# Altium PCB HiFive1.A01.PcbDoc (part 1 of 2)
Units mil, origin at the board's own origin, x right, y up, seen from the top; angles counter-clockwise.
Board outline 2700 x 2100 mil, 4 copper layers (Top Layer, GND, Power, Bottom Layer), stack 60.6 mil thick; 123 components, 93 nets, 495 pads, 264 vias.
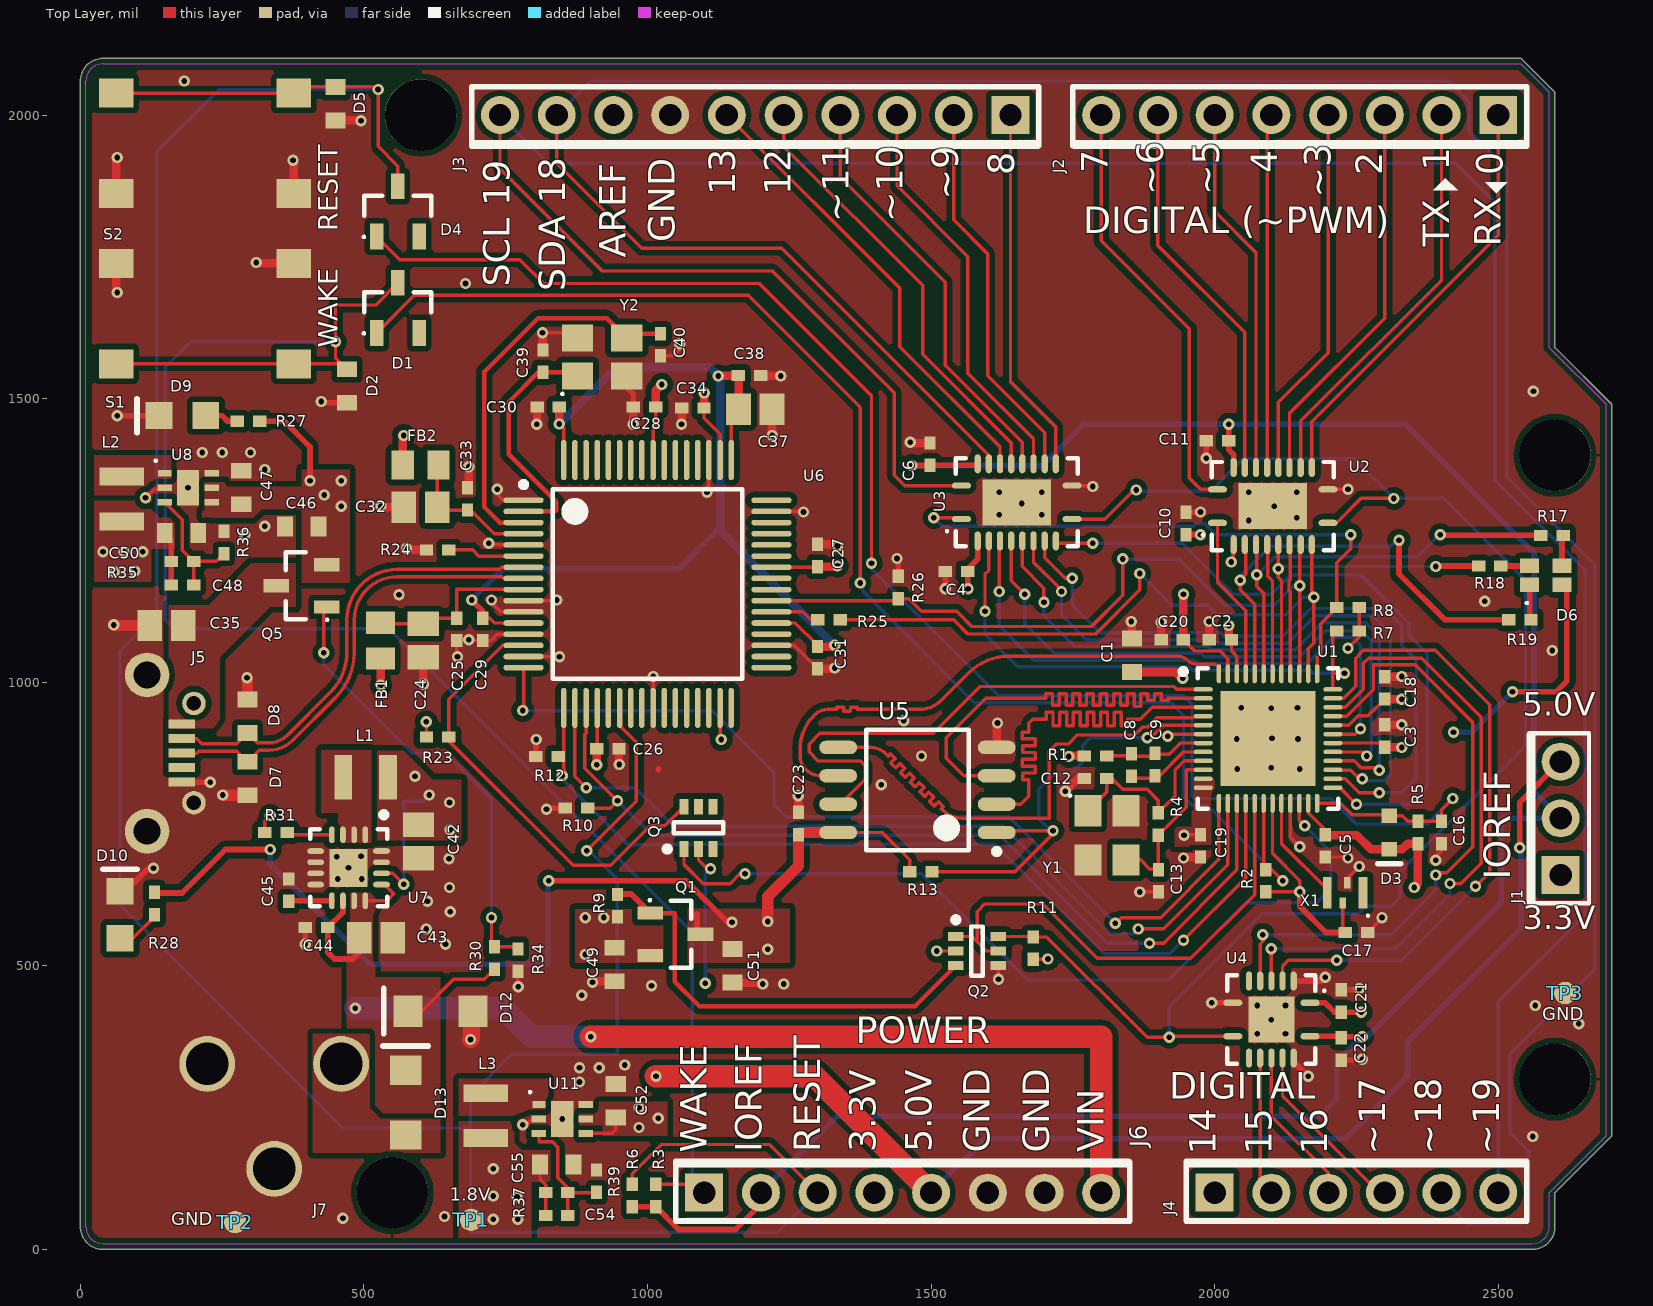
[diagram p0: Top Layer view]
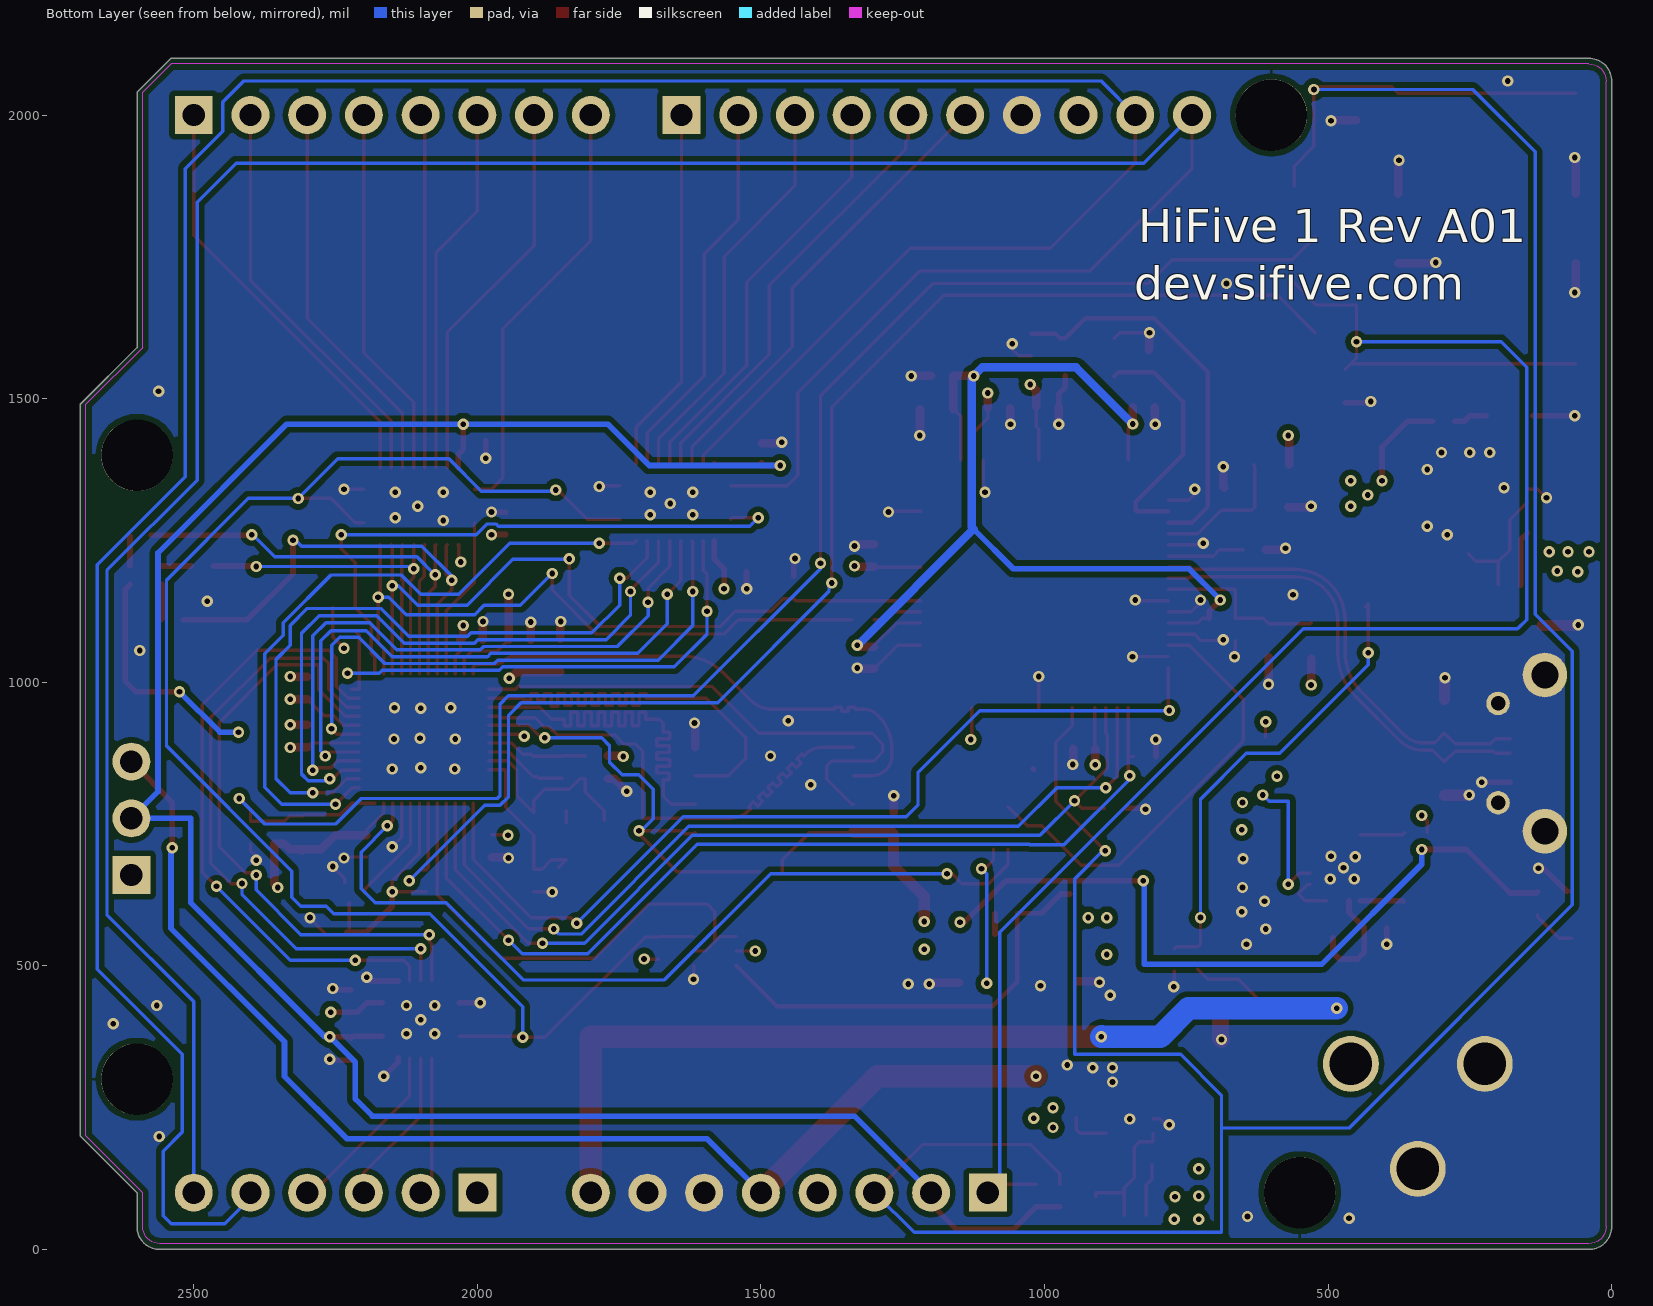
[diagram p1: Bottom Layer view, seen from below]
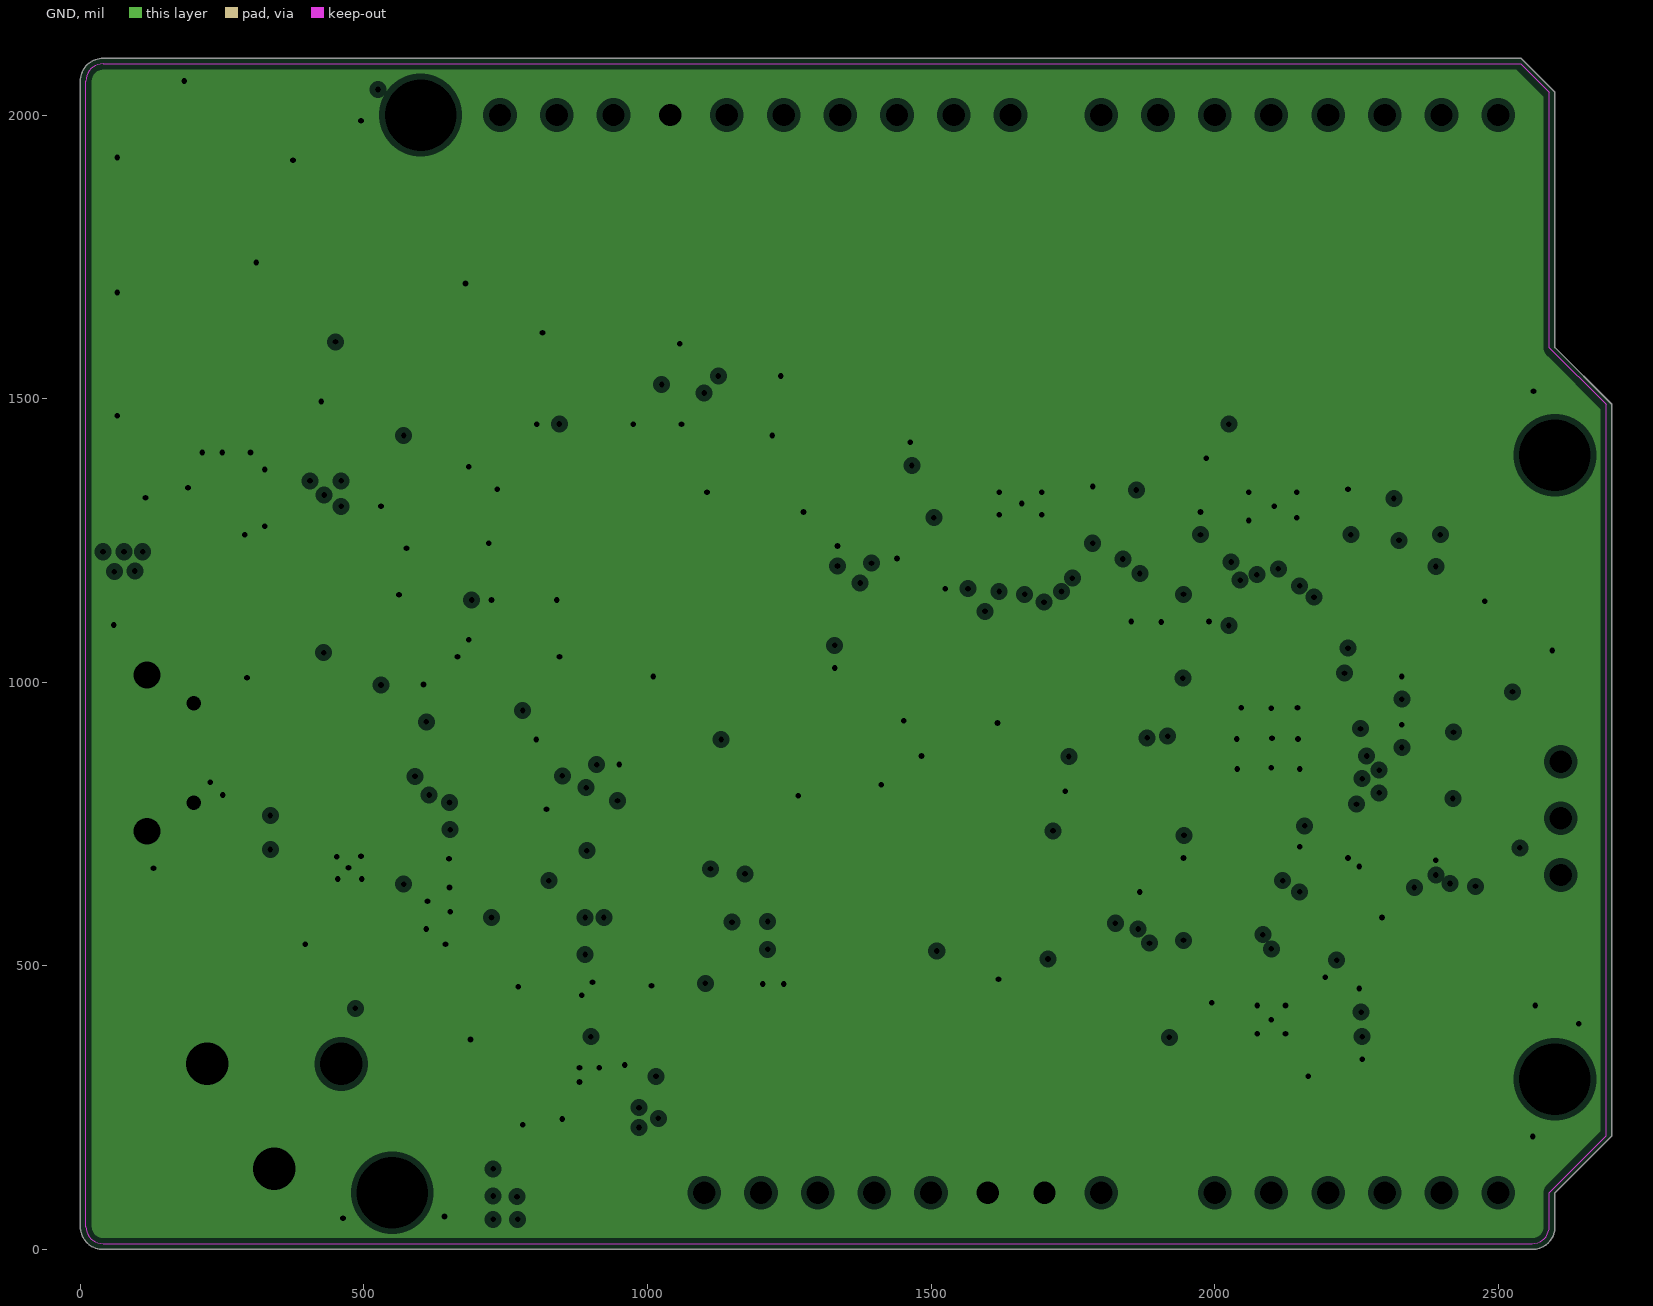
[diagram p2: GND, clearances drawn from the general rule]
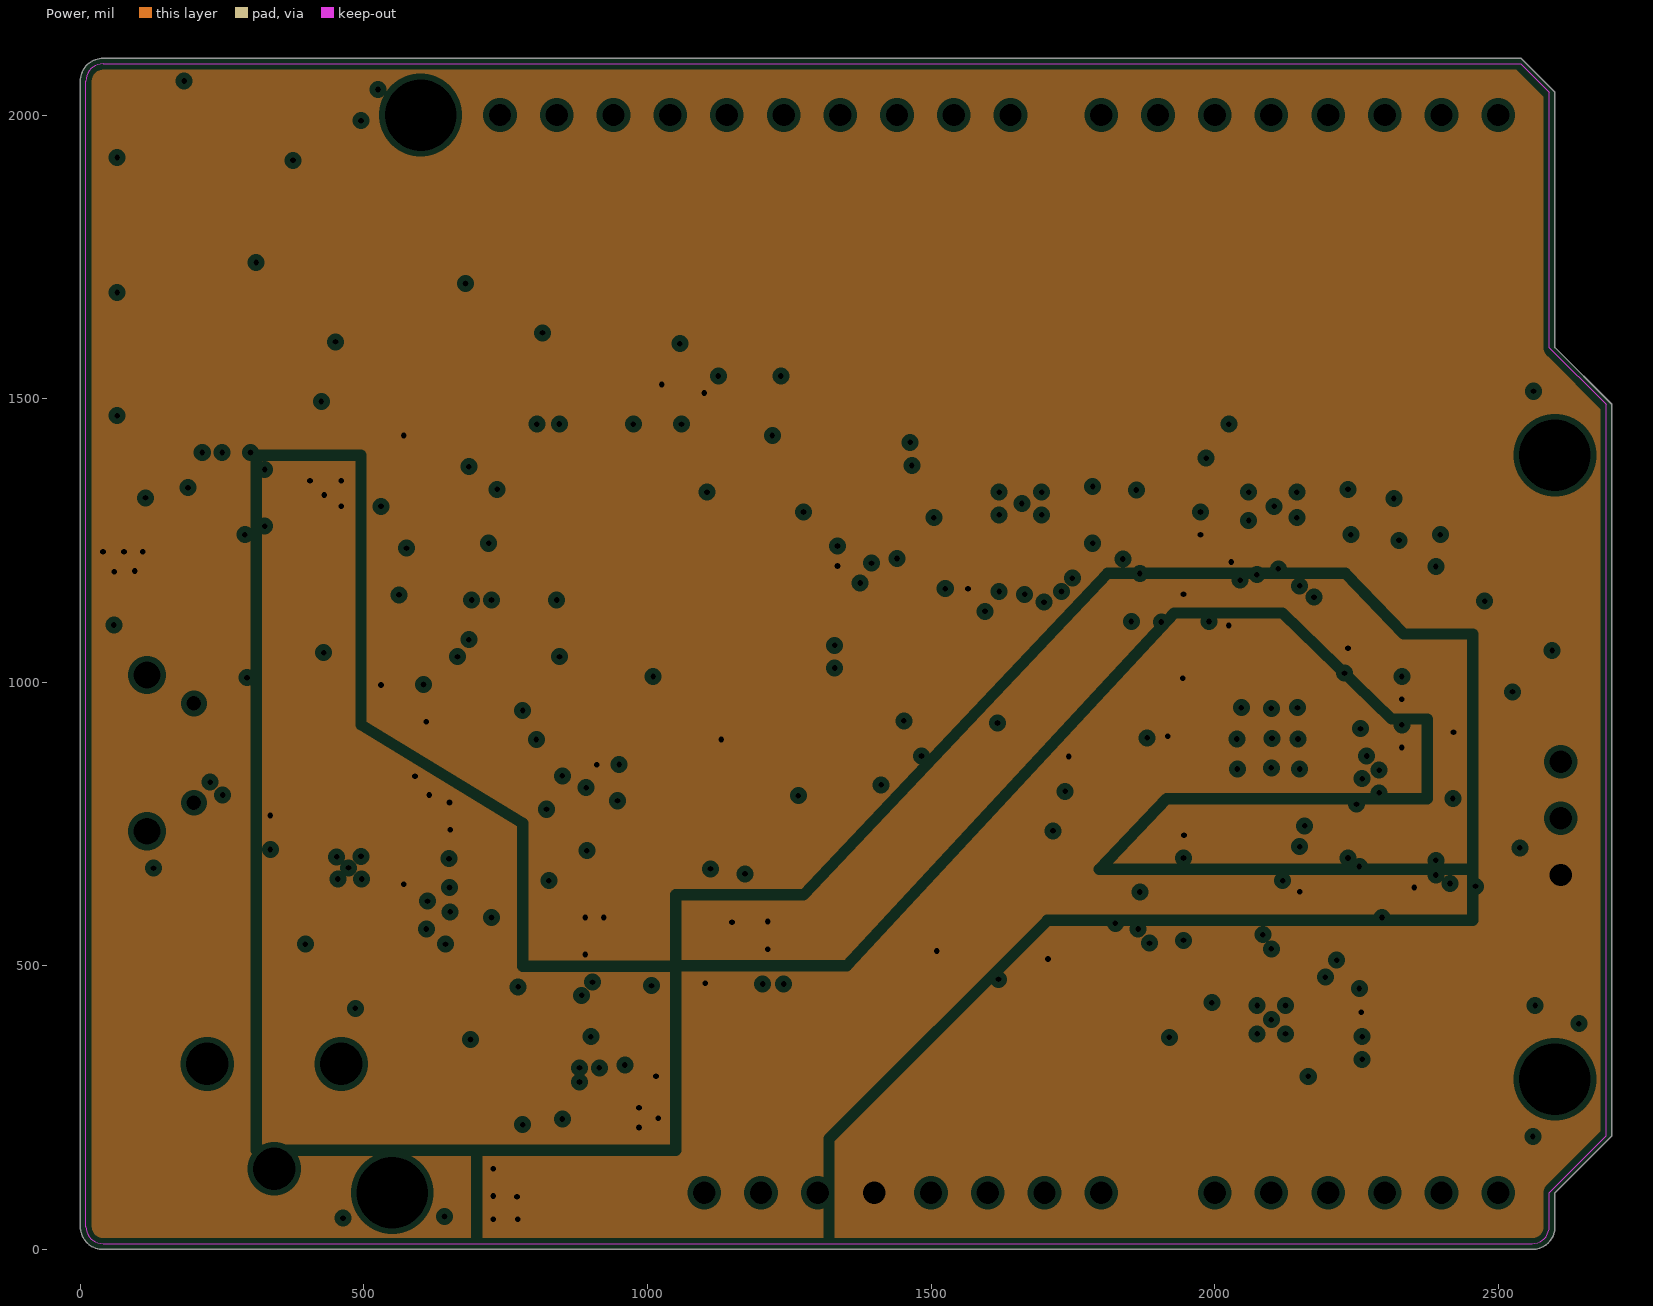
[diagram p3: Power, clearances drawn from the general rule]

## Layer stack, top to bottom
Top Solder: solder mask 0.5, Solder Resist, Dk 3.5
Top Layer: signal copper 1.4
Dielectric 1: core 4, FR-4, Dk 4.2
GND: plane copper 1.4, net GND
Dielectric 2: core 47, Dk 4.2
Power: plane copper 1.4, net (Multiple Nets)
Dielectric 3: prepreg 4, Dk 4.2
Bottom Layer: signal copper 1.4
Bottom Solder: solder mask 0.5, Solder Resist, Dk 3.5

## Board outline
0,40 0,2060 cw(c40,2060) 40,2100 2540,2100 2600,2040 2600,1590 2700,1490 2700,200 2600,100 2600,40 cw(c2560,40) 2560,0 40,0 cw(c40,40)

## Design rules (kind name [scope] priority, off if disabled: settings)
Clearance PolygonClearance [InPolygon] p1: gap=10 ignorepadtopadclearanceinfootprint=FALSE except(0: Arc-Hole Track-Hole SMDPad-Hole THPad-Hole Via-Hole Fill-Hole Poly-Hole Region-Hole Text-Hole)
Clearance [All] p2: gap=6 ignorepadtopadclearanceinfootprint=FALSE except(0: Arc-Hole Track-Hole SMDPad-Hole THPad-Hole Via-Hole Fill-Hole Poly-Hole Region-Hole Text-Hole)
ComponentClearance [All] p1: gap=1 collisioncheckmode=3 verticalgap=1 showdistances=FALSE
DiffPairsRouting DIFF90DiffPairsRouting [InDifferentialPairClass('DIFF90')] p1: maxlimit=7 minlimit=7 mostfreqgap=7 toplayer_minwidth=6 toplayer_maxwidth=6 toplayer_prefwidth=6 bottomlayer_minwidth=6 bottomlayer_maxwidth=6 bottomlayer_prefwidth=6 maxuncoupledlength=500
DiffPairsRouting [All] p2: maxlimit=10 minlimit=10 mostfreqgap=10 toplayer_minwidth=15 toplayer_maxwidth=15 toplayer_prefwidth=15 bottomlayer_minwidth=15 bottomlayer_maxwidth=15 bottomlayer_prefwidth=15 maxuncoupledlength=500
HoleSize [All] p1: absolutevalues=TRUE maxlimit=150 minlimit=1 maxpercent=80.000 minpercent=20.000
MatchedLengths QSPIMatchedLengths [InNetClass('QSPI')] p1: tolerance=50 checknetsindiffpair=FALSE checkdiffpairvsdiffpair=TRUE checkxsignals=TRUE checkothers=TRUE
MatchedLengths Diff90MatchedLengths [InDifferentialPairClass('DIFF90')] p2: tolerance=10 checknetsindiffpair=TRUE checkdiffpairvsdiffpair=FALSE checkxsignals=FALSE checkothers=FALSE
MinimumSolderMaskSliver [All] p1: minsoldermaskwidth=3
PlaneClearance [All] p1: clearance=10
PlaneConnect [All] p1: planeconnectstyle=Direct reliefexpansion=20 reliefentries=4 reliefconductorwidth=10 reliefairgap=10
PolygonConnect [All] p1: connectstyle=Direct reliefconductorwidth=10 reliefentries=4 polygonreliefangle="90 Angle" airgapwidth=10
RoutingVias [All] p1: holewidth=10 width=20 viastyle="Through Hole" minholewidth=10 minwidth=20 maxholewidth=28 maxwidth=50
SilkToSilkClearance [All] p1: silktosilkclearance=0
SilkToSolderMaskClearance [IsPad] p1: minsilkscreentomaskgap=1 clearancetoexposedcopper=TRUE
SolderMaskExpansion [All] p1: expansion=4
Width [All] p1: maxlimit=40 minlimit=6 preferedwidth=6
22 further rules are at their usual default settings.

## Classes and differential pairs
component class Freedom_E310: C1 C2 C3 C4 C5 C6 C8 C9 C10 C11 C12 C13 C16 C17 C18 C19 C20 C21 C22 C23 D1 D2 D3 D4 D5 D6 J1 J2 J3 J4 J6 Q2 R1 R2 R3 R4 R5 R6 R7 R8 R11 R13 R17 R18 R19 S1 S2 U1 U2 U3 U4 U5 X1 Y1
component class FT2232: C24 C25 C26 C27 C28 C29 C30 C31 C32 C33 C34 C35 C37 C38 C39 C40 D7 D8 FB1 FB2 J5 Q3 R10 R12 R23 R24 R25 R26 U6 Y2
component class Power: C42 C43 C44 C45 C46 C47 C48 C49 C50 C51 C52 C54 C55 D9 D10 D12 D13 GND I_VDD_1V8 J7 L1 L2 L3 Q1 Q5 R9 R27 R28 R30 R31 R34 R35 R36 R37 R39 TP1 TP2 TP3 U7 U8 U11
net class DIFF90: USB_D_N USB_D_P
net class QSPI: QSPI_CS0 QSPI_DQ0 QSPI_DQ1 QSPI_DQ2 QSPI_DQ3 QSPI_SCK
differential pair class DIFF90: USB_D
differential pair USB_D: +USB_D_P -USB_D_N

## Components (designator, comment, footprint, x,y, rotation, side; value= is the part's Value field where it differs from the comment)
C1 "10uF" C0603 1854.15,1047.53 r90 top
C2 "0.1uF" C0402 2010,1075 r180 top
C3 "0.1uF" C0402 2300,905 r90 top
C4 "0.1uF" C0402 1545,1195 r180 top
C5 "0.1uF" C0402 2195,711.49 r270 top
C6 "0.1uF" C0402 1498.38,1402 r90 top
C8 "0.1uF" C0402 1853.16,854 r270 top
C9 "0.1uF" C0402 1895,855 r270 top
C10 "0.1uF" C0402 1949.69,1280 r90 top
C11 "0.1uF" C0402 2005,1425.8 r180 top
C12 "12pF" C0402 1790,830 r180 top
C13 "12pF" C0402 1901,650 r270 top
C16 "10nF" C0402 2400,735 r270 top
C17 "0.1uF" C0402 2250,558.59 r0 top
C18 "0.1uF" C0402 2300,990 r90 top
C19 "0.1uF" C0402 1975,711.49 r270 top
C20 "0.1uF" C0402 1925.19,1075 r180 top
C21 "0.1uF" C0402 2223.2,437.94 r90 top
C22 "0.1uF" C0402 2223.2,353.12 r270 top
C23 "0.1uF" C0402 1266.19,751 r90 top
C24 "4.7uF" C0805 604.45,1073.22 r270 top
C25 "0.1uF" C0402 663.67,1093.22 r270 top
C26 "0.1uF" C0402 930,882.7 r0 top
C27 "0.1uF" C0402 1300,1223.22 r90 top
C28 "0.1uF" C0402 994.81,1485.45 r180 top
C29 "0.1uF" C0402 709.48,1093.22 r270 top
C30 "0.1uF" C0402 825,1485 r180 top
C31 "0.1uF" C0402 1300,1043.22 r270 top
C32 "4.7uF" C0805 600,1308.25 r180 top
C33 "0.1uF" C0402 682.84,1323.22 r90 top
C34 "0.1uF" C0402 1080,1483.22 r180 top
C35 "4.7uF" C0805 152,1099.89 r180 top
C37 "4.7uF" C0805 1190,1481.46 r0 top
C38 "0.1uF" C0402 1180,1540.68 r0 top
C39 "12pF" C0402 816,1566 r90 top
C40 "12pF" C0402 1023,1595 r270 top
C42 "22uF" C0805 596.13,719.07 r270 top
C43 "10uF" C0805 521,549.61 r0 top
C44 "0.1uF" C0402 416.5,567.33 r180 top
C45 "33nF" C0402 367.45,633.28 r90 top
C46 "10uF" C0603 390.47,1274.5 r180 top
C47 "10uF" C0603 283.67,1343.01 r90 top
C48 "22pF" C0402 180,1171.51 r0 top
C49 "1uF" C0603 942,502 r270 top
C50 "10uF" C0603 178.19,1263.12 r0 top
C51 "1uF" C0603 1150,500 r270 top
C52 "10uF" C0603 944,262 r90 top
C54 "22pF" C0402 840,60 r0 top
C55 "10uF" C0603 840,150 r0 top
D1 "BAT54_SOT23" SOT-23B 560,1660 r90 top value=BAT54
D2 "PGB1010603NRHF" R0603 470,1522.04 r270 top
D3 "Diode" SOD523 2307.74,735 r90 top value=1N4148WT-7
D4 "BAT54_SOT23" SOT-23B 560,1830 r90 top value=BAT54
D5 "PGB1010603NRHF" R0603 450,2020 r270 top
D6 "LED_RGB_LTST-C19HE1WT" LED0606 2584,1188.86 r0 top value=RGB
D7 "PGB1010603NRHF" R0603 294.82,830 r270 top
D8 "PGB1010603NRHF" R0603 294.82,940 r90 top
D9 "Green" LED0805 180,1470 r0 top
D10 "Green" LED0805 70,590 r270 top
D12 "SMF12A" SOD-123FL 635,420 r0 top
D13 "DB2W40300L" SOD-123FL 573.58,258.73 r270 top
FB1 "600R" R0805 529.48,1073.22 r90 top
FB2 "600R" R0805 600,1383.22 r0 top
J1 "Jumper3P" HEADER_2.54MM_3P 2610,760 r90 top
J2 "8P_IO" 8P_IO 2150,2000 r180 top locked
J3 "10P" 10P 1190,2000 r180 top locked
J4 "6P" 6P 2250,100 r0 top locked
J5 "MicroUSB2.0 Connector" UJ2-MIBH2-4-SMT 100,875 r0 top
J6 "POWER" 8P_POWER 1450,100 r0 top locked
J7 "PowerJack3P" PJ-102AH 204,327 r0 top locked
L1 "1.0uH" L252012 503,832.15 r0 top
L2 "2.2uH" L252012 72.98,1323.01 r270 top
L3 "2.2uH" L252012 715,236 r270 top
Q1 "MOSFET-P_SOT23" SOT-23B 1049.29,555.6 r0 top value=P-Channel
Q2 "DMN63D8LDW-7" SC70-6 1581,526 r0 top
Q3 "DMN63D8LDW-7" SC70-6 1090,743.22 r90 top
Q5 "MOSFET-P_SOT23" SOT-23B 390,1170 r180 top value=P-Channel
R1 "100R" R0402 1790,870 r0 top
R2 "100K" R0402 2090,650 r270 top
R3 "100K" R0402 1014.61,95 r90 top
R4 "DNP" R0402 1900.56,750 r270 top value=1M
R5 "100K" R0402 2358.49,735 r270 top
R6 "100K" R0402 973.1,95 r90 top
R7 "DNP" R0402 2235,1090 r0 top value=2K
R8 "DNP" R0402 2235,1131.51 r0 top value=2K
R9 "100K" R0402 947,606 r270 top
R10 "1K" R0402 875,778 r180 top
R11 "100K" R0402 1680,531 r90 top
R12 "1K" R0402 823,869 r180 top
R13 "100K" R0402 1482,665.93 r180 top
R17 "330R" R0402 2594.68,1258.91 r180 top
R18 "330R" R0402 2485,1205 r180 top
R19 "330R" R0402 2538,1110 r180 top
R23 "12K" R0402 630,903.22 r0 top
R24 "12K" R0402 630,1233.22 r180 top
R25 "1K" R0402 1320,1110 r0 top
R26 "1K" R0402 1442,1167 r90 top
R27 "330R" R0402 296.37,1460 r180 top
R28 "330R" R0402 130.76,610 r270 top
R30 "100K" R0402 730,513.67 r270 top
R31 "DNP" R0402 345,735 r0 top value=100K
R34 "100K" R0402 771.51,510 r90 top
R35 "820K" R0402 180,1213.01 r0 top
R36 "182K" R0402 253.16,1246.39 r90 top
R37 "360K" R0402 840,100 r0 top
R39 "180K" R0402 910,120.31 r90 top
S1 "SW-PB 4P" PTS645_SMT 220,1650 r180 top
S2 "SW-PB 4P" PTS645_SMT 220,1950 r180 top
TP1 "Testpoint" Testpoint_SMT 689,52 r270 top
TP2 "Testpoint" Testpoint_SMT 273,48 r270 top
TP3 "Testpoint" Testpoint_SMT 2618,452 r270 top
U1 "SiFive FE310-G000" QFN48_40P600X600X90_HS-49 2094.17,900.63 r0 top value=FE310-G000
U2 "TXS0108ERGYR" RGY-20 2102.41,1310.47 r90 top
U3 "TXS0108ERGYR" RGY-20 1651.1,1317.09 r90 top
U4 "TXS0104ERGYR" RGY-14 2100,405.29 r270 top
U5 "128Mbit" SOIC127P790X216-8N 1476,810 r180 top
U6 "FT2232HL" LQFP-64 1000,1173.22 r0 top
U7 "TPS62133RGTT" RGT16-1700X1700TP 472.93,672.81 r270 top
U8 "TPS62290DRVR" DRV6 190,1343.01 r0 top
U11 "TPS62290DRVR" DRV6 850,230 r0 top
X1 "32.768KHz" SITIME2012 2230,628.64 r180 top
Y1 "16 MHz" X3225 1810,730 r270 top
Y2 "12 MHz" X3225 920,1573.22 r0 top

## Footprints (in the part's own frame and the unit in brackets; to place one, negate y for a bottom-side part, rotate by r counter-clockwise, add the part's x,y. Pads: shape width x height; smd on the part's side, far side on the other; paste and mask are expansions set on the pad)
6P [mm]
  rect 1.7x1.7 hole 1: 1(-6.35,0)
  round 1.7 hole 1: 2(-3.81,0) 3(-1.27,0) 4(1.27,0) 5(3.81,0) 6(6.35,0)
  silkscreen extent -7.62,-1.27 7.62,1.52
8P_IO [mm]
  rect 1.7x1.7 hole 1: 1(-8.89,0)
  round 1.7 hole 1: 2(-6.35,0) 3(-3.81,0) 4(-1.27,0) 5(1.27,0) 6(3.81,0) 7(6.35,0) 8(8.89,0)
  silkscreen extent -10.16,-1.27 10.16,3.5
8P_POWER [mm]
  rect 1.7x1.7 hole 1: 1(-8.89,0)
  round 1.7 hole 1: 2(-6.35,0) 3(-3.81,0) 4(-1.27,0) 5(1.27,0) 6(3.81,0) 7(6.35,0) 8(8.89,0)
  silkscreen extent -10.16,-1.27 10.16,1.52
10P [mm]
  rect 1.7x1.7 hole 1: 1(-11.43,0)
  round 1.7 hole 1: 2(-8.89,0) 3(-6.35,0) 4(-3.81,0) 5(-1.27,0) 6(1.27,0) 7(3.81,0) 8(6.35,0) 9(8.89,0) 10(11.43,0)
  silkscreen extent -12.71,-1.27 12.7,1.52
C0402 [mm]
  rect 0.6x0.5 smd: 1(-0.5,0) 2(0.5,0)
C0603 [mm]
  rect 0.7x0.9 smd: 1(-0.75,0) 2(0.75,0)
C0805 [mm]
  rect 1.1x1.4 smd: 1(-0.75,0) 2(0.75,0)
DRV6 [mm]
  rect 0.6x0.3 smd paste-0.025 mask+0.07: 1(-1.05,0.65)
  rect 0.65x0.3 smd paste-0.025 mask+0.07: 2(-1.05,0) 3(-1.05,-0.65) 4(1.05,-0.65) 5(1.05,0) 6(1.05,0.65)
  rect 1x1.6 smd paste-0.5 mask+0.07: 7(0,0)
  silkscreen extent -1.5,1.15 -1.4,1.25
HEADER_2.54MM_3P [mm] "3 Pin Header; Pitch 2.54 mm (0.100 in)"
  rect 1.7x1.7 hole 1: 1(-2.54,0)
  round 1.7 hole 1: 2(0,0) 3(2.54,0)
  silkscreen extent -3.81,-1.27 3.81,1.52
L252012 [mm]
  rect 0.8x2 smd: 1(-1,0) 2(1,0)
LED0606 [mm]
  rect 0.85x0.65 smd mask+0.055: 1(-0.725,-0.425) 2(-0.725,0.425) 3(0.725,0.425) 4(0.725,-0.425)
  silkscreen extent -0.9,-1.3 -0.8,-1.2
LED0805 [mm]
  rect 1.2x1.2 smd: 1(-1.05,0) 2(1.05,0)
  silkscreen extent -2.03,-0.76 -2.03,0.76
LQFP-64 [mm]
  oval 1.8x0.25 smd mask+0.07: 1(-5.55,3.75) 2(-5.55,3.25) 3(-5.55,2.75) 4(-5.55,2.25) 5(-5.55,1.75) 6(-5.55,1.25) 7(-5.55,0.75) 8(-5.55,0.25) 9(-5.55,-0.25) 10(-5.55,-0.75) 11(-5.55,-1.25) 12(-5.55,-1.75) 13(-5.55,-2.25) 14(-5.55,-2.75) 15(-5.55,-3.25) 16(-5.55,-3.75) 33(5.55,-3.75) 34(5.55,-3.25) 35(5.55,-2.75) 36(5.55,-2.25) 37(5.55,-1.75) 38(5.55,-1.25) 39(5.55,-0.75) 40(5.55,-0.25) 41(5.55,0.25) 42(5.55,0.75) 43(5.55,1.25) 44(5.55,1.75) 45(5.55,2.25) 46(5.55,2.75) 47(5.55,3.25) 48(5.55,3.75)
  oval 0.25x1.8 smd mask+0.07: 17(-3.75,-5.55) 18(-3.25,-5.55) 19(-2.75,-5.55) 20(-2.25,-5.55) 21(-1.75,-5.55) 22(-1.25,-5.55) 23(-0.75,-5.55) 24(-0.25,-5.55) 25(0.25,-5.55) 26(0.75,-5.55) 27(1.25,-5.55) 28(1.75,-5.55) 29(2.25,-5.55) 30(2.75,-5.55) 31(3.25,-5.55) 32(3.75,-5.55) 49(3.75,5.55) 50(3.25,5.55) 51(2.75,5.55) 52(2.25,5.55) 53(1.75,5.55) 54(1.25,5.55) 55(0.75,5.55) 56(0.25,5.55) 57(-0.25,5.55) 58(-0.75,5.55) 59(-1.25,5.55) 60(-1.75,5.55) 61(-2.25,5.55) 62(-2.75,5.55) 63(-3.25,5.55) 64(-3.75,5.55)
  silkscreen extent -5.67,-4.25 4.25,4.57
PJ-102AH [mm]
  round 2.5 hole 1.9: 1(6.5,0) 2(0.5,0) 3(3.5,-4.7)
PTS645_SMT [mm]
  rect 1.55x1.3 smd: 1(-3.975,2.25) 2(3.975,2.25) 3(-3.975,-2.25) 4(3.975,-2.25)
QFN48_40P600X600X90_HS-49 [mm]
  oval 0.85x0.2 smd paste+0 mask+0.05: 1(-2.9,2.2)
  oval 0.85x0.2 smd mask+0.05: 2(-2.9,1.8) 3(-2.9,1.4) 4(-2.9,1) 5(-2.9,0.6) 6(-2.9,0.2) 7(-2.9,-0.2) 8(-2.9,-0.6) 9(-2.9,-1) 10(-2.9,-1.4) 11(-2.9,-1.8) 12(-2.9,-2.2) 25(2.9,-2.2) 26(2.9,-1.8) 27(2.9,-1.4) 28(2.9,-1) 29(2.9,-0.6) 30(2.9,-0.2) 31(2.9,0.2) 32(2.9,0.6) 33(2.9,1) 34(2.9,1.4) 35(2.9,1.8) 36(2.9,2.2)
  oval 0.2x0.85 smd mask+0.05: 13(-2.2,-2.9) 14(-1.8,-2.9) 15(-1.4,-2.9) 16(-1,-2.9) 17(-0.6,-2.9) 18(-0.2,-2.9) 19(0.2,-2.9) 20(0.6,-2.9) 21(1,-2.9) 22(1.4,-2.9) 23(1.8,-2.9) 24(2.2,-2.9) 37(2.2,2.9) 38(1.8,2.9) 39(1.4,2.9) 40(1,2.9) 41(0.6,2.9) 42(0.2,2.9) 43(-0.2,2.9) 44(-0.6,2.9) 45(-1,2.9) 46(-1.4,2.9) 47(-1.8,2.9) 48(-2.2,2.9)
  rect 4.25x4.25 smd mask+0.05: 49(0,0)
  silkscreen extent -3.92,-3.15 3.15,3.15
R0402 [mm]
  rect 0.6x0.5 smd: 1(-0.5,0) 2(0.5,0)
R0603 [mm]
  rect 0.7x0.9 smd: 1(-0.75,0) 2(0.75,0)
R0805 [mm]
  rect 1x1.3 smd: 1(-0.8,0) 2(0.8,0)
RGT16-1700X1700TP [mm]
  oval 0.75x0.25 smd paste-0.025 mask+0.07: 1(-1.475,0.75) 2(-1.475,0.25) 3(-1.475,-0.25) 4(-1.475,-0.75) 9(1.475,-0.75) 10(1.475,-0.25) 11(1.475,0.25) 12(1.475,0.75)
  oval 0.25x0.75 smd paste-0.025 mask+0.07: 5(-0.75,-1.475) 6(-0.25,-1.475) 7(0.25,-1.475) 8(0.75,-1.475) 13(0.75,1.475) 14(0.25,1.475) 15(-0.25,1.475) 16(-0.75,1.475)
  rect 1.7x1.7 smd paste-0.85 mask+0.07: 17(0,0)
  silkscreen extent -2.5,-1.73 1.73,1.73
RGY-14 [mm]
  oval 0.28x0.85 smd paste-0.025 mask+0.07: 1(-0.75,1.725) 7(-0.75,-1.725) 8(0.75,-1.725) 14(0.75,1.725)
  oval 0.85x0.28 smd paste-0.025 mask+0.07: 2(-1.725,1) 3(-1.725,0.5) 4(-1.725,0) 5(-1.725,-0.5) 6(-1.725,-1) 9(1.725,-1) 10(1.725,-0.5) 11(1.725,0) 12(1.725,0.5) 13(1.725,1)
  rect 2.05x2.05 smd paste-1.025 mask+0.07: 15(0,0)
  silkscreen extent -1.98,-1.98 1.97,2.42
RGY-20 [mm]
  oval 0.28x0.85 smd paste-0.025 mask+0.07: 1(-0.75,2.475) 10(-0.75,-2.475) 11(0.75,-2.475) 20(0.75,2.475)
  oval 0.85x0.28 smd paste-0.025 mask+0.07: 2(-1.725,1.75) 3(-1.725,1.25) 4(-1.725,0.75) 5(-1.725,0.25) 6(-1.725,-0.25) 7(-1.725,-0.75) 8(-1.725,-1.25) 9(-1.725,-1.75) 12(1.725,-1.75) 13(1.725,-1.25) 14(1.725,-0.75) 15(1.725,-0.25) 16(1.725,0.25) 17(1.725,0.75) 18(1.725,1.25) 19(1.725,1.75)
  rect 2.05x3.05 smd paste-1.025 mask+0.07: 21(0,0)
  silkscreen extent -1.97,-2.73 1.97,3.17
SC70-6 [mm]
  rect 0.7x0.4 smd mask+0.07: 1(-0.95,0.65) 2(-0.95,0) 3(-0.95,-0.65) 4(0.95,-0.65) 5(0.95,0) 6(0.95,0.65)
  silkscreen extent -1.07,-1.1 0.25,1.52
SITIME2012 [mm]
  rect 0.4x1.4 smd: 1(-0.8,0) 3(0.8,0)
  rect 0.3x0.5 smd: 2(-0.1,-0.45) 4(0.1,0.45)
  silkscreen extent -1.07,0.98 -0.98,1.07
SOD523 [mm]
  rect 0.65x0.7 smd: 1(-0.75,0) 2(0.75,0)
  silkscreen extent -1.4,-0.51 -1.4,0.51, body extent -0.65,-0.45 0.65,0.45, height 0.65
SOD-123FL [mm]
  rect 1.3x1.4 smd: 1(-1.45,0) 2(1.45,0)
  silkscreen extent -2.54,-1.02 -2.54,1.02
SOIC127P790X216-8N [mm]
  oval 1.7x0.6 smd: 1(-3.55,1.905) 2(-3.55,0.635) 3(-3.55,-0.635) 4(-3.55,-1.905) 5(3.55,-1.905) 6(3.55,-0.635) 7(3.55,0.635) 8(3.55,1.905)
  silkscreen extent -3.68,-2.7 2.3,2.88
SOT-23B [mm]
  rect 1.15x0.6 smd: 1(-1.125,0.95) 2(-1.125,-0.95) 3(1.125,0)
  silkscreen extent -1.19,-1.5 0.7,1.57
Testpoint_SMT [mm]
  round 1 smd paste+0 mask+0: 1(0,0)
UJ2-MIBH2-4-SMT [mm]
  rect 1.2x0.4 smd paste-0.025 mask+0.07: 1(2,1.3) 2(2,0.65) 3(2,0) 4(2,-0.65) 5(2,-1.3)
  round 1.05 hole 0.65 mask+0.05: 6(2.55,2.225) 7(2.55,-2.225)
  round 2 hole 1.2 mask+0.07: 8(0.45,3.5) 9(0.45,-3.5)
X3225 [mm]
  rect 1.4x1.2 smd mask+0.07: 1(-1.1,-0.85) 2(1.1,-0.85) 3(1.1,0.85) 4(-1.1,0.85)
  silkscreen extent -1.83,-1.7 -1.73,-1.6

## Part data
C1 C46 C47 C50 C52 C55: library part C0100007, "10µF 6.3V Ceramic Capacitor X5R 0603", Manufacturer="Murata Electronics", Manufacturer PN=GRM188R60J106ME47J
C2 C3 C4 C5 C6 C8 C9 C10 C11 C17 C18 C19 C20 C21 C22 C23 C25 C26 C27 C28 C29 C30 C31 C33 C34 C38 C44: library part C0100004, "0.10µF 16V Ceramic Capacitor X7R 0402", Manufacturer="Murata Electronics", Manufacturer PN=GRM155R71C104KA88J
C12 C13 C39 C40: library part C0100012, "CAP CER 12PF 50V NP0 0402", Manufacturer="Murata Electronics", Manufacturer PN=GRM1555C1H120JA01D
C16: library part C0100014, "10nF 50V Ceramic Capacitor X5R 0402", Manufacturer="Murata Electronics", Manufacturer PN=GRM155R71H103KA88D
C24 C32 C35 C37: library part C0100013, "4.7µF 16V Ceramic Capacitor X5R 0805", Manufacturer="Murata Electronics", Manufacturer PN=GRM21BR61C475KA88L
C42: library part C0100010, "22µF 6.3V Ceramic Capacitor X5R 0805", Manufacturer="Murata Electronics", Manufacturer PN=GRM21BR60J226ME39L
C43: library part C0100015, "10µF ±10% 25V Ceramic Capacitor X5R 0805", Manufacturer="Murata Electronics", Manufacturer PN=GRM21BR61E106KA73L
C45: library part C0100011, "33nF 25V Ceramic Capacitor X7R 0402", Manufacturer="Murata Electronics", Manufacturer PN=GRM155R71E333KA88D
C48 C54: library part C0100009, "22pF 50V Ceramic Capacitor C0G, NP0 0402", Manufacturer="Murata Electronics", Manufacturer PN=GRM1555C1H220JA01J
C49 C51: library part C0100006, "1µF 16V Ceramic Capacitor X5R 0603", Manufacturer="Murata Electronics", Manufacturer PN=GRM188R61C105KA93D
D1 D4: library part D0000004, "Diode Schottky 30V 200mA Surface Mount SOT-23-3 (TO-236)", Manufacturer="Fairchild Semiconductor", Manufacturer PN=BAT54
D2 D5 D7 D8: library part D0000003, "TVS DIODE 24VWM 150VC 0603", Manufacturer="Littelfuse Inc"
D3: library part D0000001, "Diode Standard 80V 125mA Surface Mount SOD-523", Manufacturer="Diodes Incorporated", Manufacturer PN=1N4148WT-7
D6: library part E0000005, "Red, Green, Blue (RGB) 624nm Red, 525nm Green, 470nm Blue LED Indication - Discrete 1.8V Red, 2.8V Green, 2.8V Blue 0606", Manufacturer="Lite-on Inc.", Manufacturer PN=LTST-C19HE1WT
D9 D10: library part E0000001, "Green 570nm LED Indication - Discrete 2.2V 0805", Manufacturer="OSRAM Opto Semiconductors Inc", Manufacturer PN="LG R971-KN-1"
D12: library part D0000002, "TVS DIODE 12VWM 19.9VC SOD123", Manufacturer="Littelfuse Inc"
D13: library part D0000006, "Diode Schottky 40V 3A (DC) Surface Mount", Manufacturer="Panasonic Electronic Components"
FB1 FB2: library part F0000001, "FERRITE BEAD 600 OHM 0805", Manufacturer="Laird-Signal Integrity Products", Manufacturer PN=HZ0805E601R-10
J1: library part J0000014, "3 Positions Header, Unshrouded, Breakaway Connector 0.100\" (2.54mm) Through Hole Tin", Manufacturer="Harwin Inc", Manufacturer PN=M20-9770346
J2: "8 Pin I/O Connector", Manufacturer="Sullins Connector Solutions", Manufacturer PN=PPTC081LFBN-RC
J3: "10 Pin Connector", Manufacturer="Sullins Connector Solutions", Manufacturer PN=PPTC101LFBN-RC
J4: "Connector", Manufacturer="Sullins Connector Solutions", Manufacturer PN=PPTC061LFBN-RC
J5: "USB - micro B USB 2.0 Receptacle Connector 5 Position Surface Mount, Right Angle, Horizontal", Manufacturer="CUI Inc", Manufacturer PN=UJ2-MIBH2-4-SMT
J6: library part 8P_POWER, "Power Connector", Manufacturer="Sullins Connector Solutions", Manufacturer PN=PPTC081LFBN-RC
J7: library part J0000003, "Power Barrel Connector Jack 2.00mm ID (0.079\"), 5.50mm OD (0.217\") Through Hole, Right Angle", Manufacturer="CUI Inc", Manufacturer PN=PJ-102AH
L1: library part L0000003, "1µH Shielded Inductor 3.3A 40 mOhm", Manufacturer="Murata Electronics", Manufacturer PN=DFE252012F-1R0M=P2
L2 L3: library part L0000002, "2.2µH Shielded Wirewound Inductor 3A 84 mOhm", Manufacturer="Murata Electronics", Manufacturer PN=DFE252012P-2R2M=P2
Q1 Q5: library part Q0000002, "MOSFET P-CH 20V 3.7A SOT-23", Manufacturer="Infineon Technologies", Manufacturer PN=IRLML6402TRPBF
Q2 Q3: library part Q0000003, "MOSFET 2N-CH 30V 0.22A SOT363", Manufacturer="Diodes Inc"
R1: library part R0000020, "RES SMD 100 OHM 1% 1/16W 0402", Manufacturer=Yageo, Manufacturer PN=RC0402FR-07100RL
R2 R3 R5 R6 R9 R11 R13 R30 R31 R34: library part R0000012, "RES SMD 100K OHM 1% 1/16W 0402", Manufacturer=Yageo, Manufacturer PN=RC0402FR-07100KL
R4: library part R0000021, "RES SMD 1M OHM 1% 1/16W 0402", Manufacturer=Yageo, Manufacturer PN=RC0402FR-071ML
R7 R8: library part R0000025, "RES SMD 2K OHM 1% 1/16W 0402", Manufacturer=Yageo, Manufacturer PN=RC0402FR-072KL
R10 R12 R25 R26: library part R0000019, "RES SMD 1K OHM 1% 1/16W 0402", Manufacturer=Yageo, Manufacturer PN=RC0402FR-071KL
R17 R18 R19 R27 R28: library part R0000026, "RES SMD 330 OHM 1% 1/16W 0402", Manufacturer=Yageo, Manufacturer PN=RC0402FR-07330RL
R23 R24: library part R0000023, "RES SMD 12K OHM 1% 1/16W 0402", Manufacturer=Yageo, Manufacturer PN=RC0402FR-0712KL
R35: library part R0000017, "RES SMD 820K OHM 1% 1/16W 0402", Manufacturer=Yageo, Manufacturer PN=RC0402FR-07820KL
R36: library part R0000018, "RES SMD 182K OHM 1% 1/16W 0402", Manufacturer=Yageo, Manufacturer PN=RC0402FR-07182KL
R37: library part R0000015, "RES SMD 360K OHM 1% 1/16W 0402", Manufacturer=Yageo, Manufacturer PN=RC0402FR-07360KL
R39: library part R0000014, "RES SMD 180K OHM 1% 1/16W 0402", Manufacturer=Yageo, Manufacturer PN=RC0402FR-07180KL
S1: library part M0000004, "Blue Tactile Switch SPST-NO Top Actuated Surface Mount", Manufacturer="C & K Components", Manufacturer PN="PTS645SM43SMTR92 LFS"
S2: library part M0000003, "Red Tactile Switch SPST-NO Top Actuated Surface Mount", Manufacturer="C & K Components", Manufacturer PN="PTS645SK43SMTR92 LFS"
TP1 TP2 TP3: library part M0000002, "Test Point SMT"
U1: library part Freedom-E310, Manufacturer=SiFive, Manufacturer PN=FE310-G000-A01
U2 U3: library part U0000010, "Voltage Level Translator Bidirectional 1 Circuit 8 Channel 60Mbps 20-VQFN (3.5x4.5)", Manufacturer="Texas Instruments"
U4: library part U0000009, "Voltage Level Translator Bidirectional 1 Circuit 4 Channel 24Mbps 14-VQFN (3.5x3.5)", Manufacturer="Texas Instruments"
U5: library part U0000011, "IC FLASH 128MBIT 133MHZ 8SOIC", Manufacturer=ISSI, Manufacturer PN=IS25LP128-JBLE
U6: library part U0000001, "IC USB Bridge, USB to UART,FIFO USB 2.0 UART Interface 64-LQFP", Manufacturer=FTDI, Manufacturer PN=FT2232HL-REEL
U7: library part U0000007, "Buck Switching Regulator IC Positive Fixed 5V 1 Output 3A 16-VFQFN Exposed Pad", Manufacturer="Texas Instruments"
U8 U11: library part U0000006, "Buck Switching Regulator IC Positive Adjustable 0.6V 1 Output 1A 6-WDFN Exposed Pad", Manufacturer="Texas Instruments"
X1: library part X0000003, "32.768kHz LVCMOS MEMS (Silicon) Oscillator Surface Mount 1.2 V ~ 3.63 V 1.3µA", Manufacturer=SiTime, Manufacturer PN=SIT1533AC-H5-D14-32.768D
Y1: library part X0000002, "16MHz ±30ppm Crystal 12pF 80 Ohm", Manufacturer="TXC Corporation", Manufacturer PN=7M-16.000MAAE-T
Y2: library part X0000004, "12MHz ±30ppm Crystal 10pF 120 Ohm -20°C ~ 70°C", Manufacturer="Abracon LLC", Manufacturer PN=ABM8G-12.000MHZ-B4Y-T

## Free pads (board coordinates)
  round 125.98 hole 125.98 unplated paste-0.98 mask+2.76: Mech1(550,100)
  round 125.98 hole 125.98 unplated paste+0 mask+0: Mech2(600,2000) Mech3(2600,1400) Mech4(2600,300)

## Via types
v1: diameter 20, hole 10, Top Layer to Bottom Layer, tented both sides, 264 vias

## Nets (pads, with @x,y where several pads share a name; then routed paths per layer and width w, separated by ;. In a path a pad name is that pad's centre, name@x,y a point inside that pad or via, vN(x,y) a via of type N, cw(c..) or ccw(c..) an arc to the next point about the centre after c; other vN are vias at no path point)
AON_ERST_N: C16.1 D3.2 D4.1 R5.1 U1.24 | length 2899.1
  Top Layer w6: D4.1@522.6,1785.71 563.31,1745 775,1745 817,1703 1197,1703 1395,1505 v1(1395,1210) ; U1.24@2180.79,786.46 2221.67,786.46 2242.13,766 2306.26,766 D3.2@2307.74,764.53 2330.47,764.53 2340.32,754.68 R5.1@2358.49,754.68 C16.1@2400,754.68 2400,775 v1(2420,795)
  Bottom Layer w6: v1(1395,1210) 1395,1200 1619,976 1945.13,976 1960,961.13 1960,800 1965,795 2205,795 2250,750 2375,750 v1(2420,795)
AON_PMU_DWAKEUP_N: D1.1 R2.1 U1.18 | length 2480.6
  Top Layer w6: D1.1@522.6,1615.71 588.89,1682 1178,1682 1375,1485 v1(1375,1175) ; U1.18@2086.3,786.46 2086.3,673.39 R2.1@2090,669.68 2100.32,669.68 v1(2120,650)
  Bottom Layer w6: v1(1375,1175) 1380,1170 1380,1160 1576,964 1923,964 1945,942 1945,798.03 1960.03,783 1987,783 v1(2120,650)
DCIN_DET: Q5.1 R30.1 R34.2 | length 814.3
  Top Layer w6: v1(429,1052) 429,1137.89 Q5.1@434.29,1132.6 ; v1(725,585) 725,538.36 R30.1@730,533.36 767.83,533.36 R34.2@771.51,529.69
  Bottom Layer w6: v1(429,1052) 429,1031 585,875 644,875 725,794 v1(725,585)
DIG0: J2.1 U2.12 | length 757.8
  Top Layer w6: U2.12@2171.31,1378.39 2171.31,1459.31 2500,1788 J2.1@2500,2000
DIG1: J2.2 U2.13 | length 724.5
  Top Layer w6: U2.13@2151.62,1378.39 2151.62,1460.62 2400,1709 J2.2@2400,2000
DIG2: J2.3 U2.14 | length 691.2
  Top Layer w6: U2.14@2131.94,1378.39 2131.94,1473.94 2300,1642 J2.3@2300,2000
DIG3: J2.4 U2.15 | length 658
  Top Layer w6: U2.15@2112.25,1378.39 2112.25,1493.25 2200,1581 J2.4@2200,2000
DIG4: J2.5 U2.16 | length 624.7
  Top Layer w6: U2.16@2092.57,1378.39 2092.57,1992.57 J2.5@2100,2000
DIG5: J2.6 U2.17 | length 651.8
  Top Layer w6: J2.6@2000,2000 2000,1830 2072.88,1757.12 U2.17@2072.88,1378.39
DIG6: J2.7 U2.18 | length 685.1
  Top Layer w6: J2.7@1900,2000 1900,1770 2053.2,1616.8 U2.18@2053.2,1378.39
DIG7: J2.8 U2.20 | length 762.5
  Top Layer w6: J2.8@1800,2000 1800,1778 1955,1623 1955,1360 1975,1340 U2.20@2004.97,1340
DIG8: J3.1 U3.12 | length 648.1
  Top Layer w6: J3.1@1640,2000 1640,1530 1720,1450 U3.12@1720,1385
DIG9: J3.2 U3.13 | length 681.4
  Top Layer w6: J3.2@1540,2000 1540,1815 1600,1755 1600,1540 1700.32,1439.68 U3.13@1700.32,1385
DIG10: J3.3 U3.14 | length 714.7
  Top Layer w6: J3.3@1440,2000 1440,1875 1565,1750 1565,1545 1680.63,1429.37 U3.14@1680.63,1385
DIG11: J3.4 U3.15 | length 747.9
  Top Layer w6: J3.4@1340,2000 1340,1890 1525,1705 1525,1559.16 1660.94,1423.22 U3.15@1660.94,1385
DIG12: J3.5 U3.16 | length 781.2
  Top Layer w6: J3.5@1240,2000 1240,1958.03 1245,1953.03 1245,1940 1485,1700 1485,1578.03 1641.26,1421.77 U3.16@1641.26,1385
DIG13: J3.6 U3.17 | length 814.5
  Top Layer w6: J3.6@1140,2000 1445,1695 1445,1591.24 1621.57,1414.67 U3.17@1621.57,1385
DIG15: J4.2 U4.10 | length 245.5
  Top Layer w6: U4.10@2080.31,337.38 2080.31,119.69 J4.2@2100,100
DIG16: J4.3 U4.11 | length 278.8
  Top Layer w6: U4.11@2100,337.38 2100,235 2200,135 J4.3@2200,100
DIG17: J4.4 U4.12 | length 317.9
  Top Layer w6: U4.12@2119.68,337.38 2119.68,270.32 2290,100 J4.4@2300,100
DIG18: J3.9 J4.5 U3.18 | length 5044.5
  Top Layer w6: J3.9@840,2000 840,1915 990,1765 1236.66,1765 1601.89,1399.77 U3.18@1601.89,1385
  Bottom Layer w6: J3.9@840,2000 900,2060 2412,2060 2449,2023 2449,1971.34 2515,1905.34 2515,1362 2670,1207 2670,494 2520,344 2520,207 2554,173 2554,59 2540,45 2445,45 2400,90 J4.5@2400,100
DIG19: J3.10 J4.6 U3.20 | length 4917.9
  Top Layer w6: J3.10@740,2000 740,1905 920,1725 1220,1725 1435,1510 1435,1365 1453.39,1346.61 U3.20@1553.66,1346.61
  Bottom Layer w6: J3.10@740,2000 825,1915 2425,1915 2494,1846 2494,1356 2653,1197 2653,590 2500,437 J4.6@2500,100
FT_RESET: Q3.1 U1.22 | length 1506.5
  Top Layer w6: Q3.1@1064.41,705.82 1064.41,678.59 1098,645 1146,645 1163,662 v1(1172,662) ; U1.22@2149.29,786.46 2149.29,756.2 v1(2158.66,746.82)
  Bottom Layer w6: v1(1172,662) 1483,662 1670,475 1919,475 2055,611 2180,611 2205,636 2205,700.49 v1(2158.66,746.82)
FT_UART_TX: R25.1 U6.38 | length 87.6
  Top Layer w6: U6.38@1218.5,1124.01 1274.01,1124.01 1288.01,1110 R25.1@1300.32,1110
GND: C1.2 C2.2 C3.2 C4.2 C5.2 C6.2 C10.2 C11.2 C12.2 C13.2 C16.2 C17.2 C18.2 C19.2 C20.2 C21.2 C22.2 C23.2 C24.2 C25.2 C26.2 C27.2 C28.2 C29.2 C30.2 C31.2 C32.2 C33.2 C34.2 C35.2 C37.2 C38.2 C39.2 C40.2 C42.2 C43.2 C44.2 C45.2 C46.2 C47.2 C49.2 C50.2 C51.2 C52.2 C55.2 D2.2 D5.2 D7.2 D8.2 D9.1 D10.1 D12.2 J3.7 J5.5 J5.6 J5.7 J5.8 J5.9 J6.6 J6.7 J7.2 J7.3 Q2.4 R10.2 R12.2 R24.2 R26.2 R34.1 R36.2 R39.2 S1.3 S1.4 S2.1 S2.2 TP2.1 TP3.1 U1.21 U1.49 U2.11 U2.21 U3.11 U3.21 U4.2 U4.7 U4.13 U4.15 U5.4 U6.1 U6.5 U6.10 U6.11 U6.13 U6.15 U6.25 U6.35 U6.47 U6.51 U7.5 U7.6 U7.7 U7.8 U7.15 U7.16 U7.17 U8.2 U8.6 U8.7 U11.2 U11.6 U11.7 X1.2 Y1.2 Y1.4 Y2.2 Y2.4 | length 3433.7
  Top Layer w6: D10.1@70,631.34 D10.1@79.34,631.34 ; v1(115,1325) 130,1340 145.65,1340 U8.2@148.66,1343.01 ; C25.2@663.67,1073.53 663.67,1046.33 v1(665,1045) ; v1(685,1075) 686.47,1073.53 C29.2@709.48,1073.53 724.26,1073.53 735.36,1084.64 U6.13@781.5,1084.64 ; v1(720,1245) 722.88,1242.12 U6.5@781.5,1242.12 ; v1(725,1145) 725,1140 740.99,1124.01 U6.11@781.5,1124.01 ; v1(735,1340) 735,1331.71 745.86,1320.86 U6.1@781.5,1320.86 ; R34.1@771.51,490.32 771.51,463.49 v1(772,463) ; v1(780,220) 780,213 797,230 U11.2@808.66,230 ; U6.15@781.5,1045.27 844.73,1045.27 v1(845,1045) ; U6.10@781.5,1143.69 838.69,1143.69 v1(840,1145) ; v1(815,1616) 867.38,1616 Y2.4@876.69,1606.68 ; v1(903,471) v1@904.47,472.47 ; U6.25@1009.84,954.71 1009.84,1009.84 v1(1010,1010) ; C40.2@1023,1575.31 1045.31,1575.31 1057,1587 v1(1057,1597) ; v1(1105,1335) 1108.27,1338.27 U6.51@1108.27,1391.72 ; v1@1200.53,470.47 v1(1203,468) ; U6.35@1218.5,1064.95 1258.58,1064.95 C31.2@1300,1023.53 ; U6.47@1218.5,1301.17 1273.83,1301.17 v1(1275,1300) ; Q2.4@1618.4,500.41 1618.4,476.6 v1(1619,476) ; U3.11@1748.54,1346.61 1783.39,1346.61 v1(1785,1345) ; Y1.4@1843.46,752.54 Y1.4@1843.46,773.31 ; v1(1868,630) 1868.31,630.31 C13.2@1901,630.31 ; U1.21@2133.54,786.46 2133.54,726.46 v1(2150,710) ; C5.2@2195,691.8 2233.2,691.8 v1(2235,690) ; U2.11@2199.85,1340 v1(2235,1340) ; X1.2@2233.94,646.36 2233.94,653.94 v1(2255,675) ; C17.2@2269.69,558.59 2295,583.91 v1(2295,585) ; v1(2390,686) 2390,693 2400,703 C16.2@2400,715.31 ; v1@2395,685 v1@2396.5,686.5
  Top Layer w10: v1(65,1470) D9.1@138.66,1470 ; D10.1@79.34,631.34 120,672 v1(129,672) ; J5.5@178.74,823.82 v1(228.82,823.82) ; v1(396.82,538.18) C44.2@396.82,567.33 ; v1(425,1495) 427.49,1492.51 D2.2@470,1492.51 ; R12.2@803.31,869 803.31,898.31 v1(804,899) ; v1(822,776) 824,778 R10.2@855.31,778 ; Y2.2@963.31,1539.75 963.31,1519.69 975.13,1507.87 C28.2@975.13,1485.45 ; 1019.01,846.01 1020,847 ; v1(1440,1218) 1442,1216 R26.2@1442,1186.69 ; v1(1525,1165) 1525.31,1165.31 C4.2@1525.31,1195 ; C10.2@1949.68,1299.69 1974.69,1299.69 v1(1975,1300) ; v1(1985,1395) 1985.31,1395.31 C11.2@1985.31,1425.8 ; v1(1995,435) 1995.18,434.82 U4.7@2032.08,434.82 ; U4.13@2139.37,337.38 2139.37,330.63 v1(2165,305) ; U4.2@2139.37,473.2 2188.2,473.2 v1(2195,480) ; C22.2@2223.2,333.44 2258.44,333.44 v1(2260,335) ; C21.2@2223.2,457.62 2252.62,457.62 v1(2255,460)
  Top Layer w15: S1.4@63.5,1738.58 63.5,1688.5 v1(65,1687.01) ; S2.2@63.5,1861.42 63.5,1923.5 v1(65,1925) ; v1(310,1740) 311.42,1738.58 S1.3@376.5,1738.58 ; v1(375,1920) 376.5,1918.5 S2.1@376.5,1861.42 ; D5.2@450,1990.47 494.53,1990.47 v1(495,1990) ; v1(530,1310) 531.75,1308.25 C32.2@570.47,1308.25 ; v1(575,1236.44) 571.78,1233.22 R24.2@610.31,1233.22 ; C24.2@604.45,1043.69 604.45,995.55 v1(605,996.1) ; C33.2@682.84,1342.9 685,1345.06 v1(685,1380) ; v1(805,1455) 805.31,1455.31 C30.2@805.31,1485 ; v1(815,1616) 815,1586.68 C39.2@816,1585.69 ; v1@904.47,472.47 C49.2@942,472.47 ; C26.2@949.69,882.7 949.69,855.31 v1(950,855) ; v1(975,1455) 975.13,1455.13 C28.2@975.13,1485.45 ; v1(1060,1455) 1060.31,1455.31 C34.2@1060.31,1483.22 ; C51.2@1150,470.47 v1@1200.53,470.47 ; C38.2@1199.69,1540.68 1234.32,1540.68 v1(1235,1540) ; C37.2@1219.53,1481.46 1219.53,1435.47 v1(1220,1435) ; v1(1266,800) 1266.19,799.81 C23.2@1266.19,770.69 ; C31.2@1300,1023.53 1328.53,1023.53 v1(1330,1025) ; C27.2@1300,1242.9 1332.1,1242.9 v1(1335,1240) ; v1(1463,1423) 1464.31,1421.69 C6.2@1498.38,1421.69 ; U5.4@1615.76,885 1615.76,926.76 v1(1617,928) ; v1(1736.49,807.49) 1759,830 C12.2@1770.31,830 ; v1(1853,1107) 1854.15,1105.85 C1.2@1854.15,1077.06 ; C20.2@1905.5,1075 1905.5,1105.5 v1(1906,1106) ; v1(1945,690) 1946.8,691.8 C19.2@1975,691.8 ; v1(1990,1107) 1990.31,1106.69 C2.2@1990.31,1075 ; C3.2@2300,924.68 2300.31,925 v1(2330,925) ; C18.2@2300,1009.69 2329.69,1009.69 v1(2330,1010)
  Top Layer w20: v1(59,1101) 60.11,1099.89 C35.2@122.47,1099.89 ; v1(251,801) 251.53,800.47 D7.2@294.82,800.47 ; v1(294,1008) 294.82,1007.18 D8.2@294.82,969.53
  Top Layer w30: v1(688,370) 689.4,371.4 D12.2@689.4,420
  other v1: 463,55 642,58 2561,199 850,230 880,295 880,320 915,320 960,325 2075,380 2125,380 2642,398 2100,405 2075,430 2125,430 2565,430 884,448 1007,465 1240,468 644,538 610,565 652,595 612,614 651,638 454,653 496,653 472.93,672.81 650,689 452,692 495,693 1412,819 2040,847 2150,847 2100,849 1483,870 2039,900 2147,900 2101,901 1452,932 2100,954 2047,955 2146,955 2595,1056 2476,1143 562,1154 290,1260 325,1275 2060,1285 2145,1290 1620,1295 1695,1295 2105,1310 1660,1315 1620,1335 1695,1335 2060,1335 2145,1335 190,1343.01 325,1375 215,1405 250,1405 300,1405 2562,1513 679,1703 183,2060
GPIO_0: U1.25 U3.9 | length 1210.3
  Top Layer w6: U3.9@1720,1249.17 1724.17,1245 v1(1785,1245) ; U1.25@2208.35,814.02 2220.98,814.02 v1(2250,785)
  Bottom Layer w6: v1@1789,1241 v1(1785,1245) 1943,1245 2033,1155 2100,1155 2134,1189 2257.97,1189 2342,1104.97 2342,1083 2375,1050 2375,815 2345,785 v1(2250,785)
GPIO_1: U1.26 U3.8 | length 1229.3
  Top Layer w6: U3.8@1700.32,1249.17 1700.32,1219.68 1736.5,1183.5 v1(1749,1183.5) ; U1.26@2208.35,829.76 2230.24,829.76 2255,805 v1(2290,805)
  Bottom Layer w6: v1@1753.5,1183.5 v1(1749,1183.5) 1749,1136 1798,1087 2011.13,1087 2017.13,1081 2121,1081 2170,1130 2300,1130 2330,1100 2330,1065 2355,1040 2355,830 2330,805 v1(2290,805)
GPIO_2: U1.27 U3.7 | length 1147.3
  Top Layer w6: U3.7@1680.63,1249.17 1680.63,1211.24 1730,1161.87 v1(1730,1160) ; U1.27@2208.35,845.51 2208.86,845 2240,845 2255,830 v1(2260,830)
  Bottom Layer w6: v1(1730,1160) 1730,1118 1773,1075 1999,1075 2005,1069 2129,1069 2177,1117 2279,1117 2310,1086 2310,838.13 2297.87,826 2264,826 v1(2260,830)
GPIO_3: U1.28 U3.6 | length 1118.5
  Top Layer w6: U3.6@1660.94,1249.17 1660.94,1204.06 1699,1166 v1(1699,1141) ; U1.28@2208.35,861.26 2245.74,861.26 2258,849 2286,849 v1(2290,845)
  Bottom Layer w6: v1(1699,1141) 1699,1117 1753,1063 1989,1063 1995,1057 2142,1057 2190,1105 2266.87,1105 2290,1081.87 v1(2290,845)
GPIO_4: U1.29 U3.5 | length 1086.4
  Top Layer w6: U3.5@1641.26,1249.17 1641.26,1178.74 v1(1665,1155) ; U1.29@2208.35,877.01 2260.99,877.01 v1(2268,870)
  Bottom Layer w6: v1(1665,1155) 1665,1103 1717,1051 1976,1051 1982,1045 2150,1045 2196,1091 2258,1091 2276,1073 2276,878 v1(2268,870)
GPIO_5: U1.31 U3.4 | length 1038.9
  Top Layer w6: v1(1620,1160) 1620,1247.6 U3.4@1621.57,1249.17 ; U1.31@2208.35,908.5 2247.5,908.5 v1(2257,918)
  Bottom Layer w6: v1(1620,1160) 1620,1100 1681,1039 1964,1039 1970,1033 2163,1033 2209,1079 2242.87,1079 2257,1064.87 v1(2257,918)
GPIO_9: U1.33 U4.5 | length 1103.9
  Top Layer w6: U4.5@2080.31,473.2 2080.31,538.31 2085,543 v1(2085,555) ; U1.33@2208.35,940 2233.12,940 2280,986.88 2280,1030.5 2353.5,1030.5 2455,929 2455,710 2409,664 2394,664 v1(2390,660)
  Bottom Layer w6: v1(2085,555) 2311,555 2390,634 v1(2390,660)
GPIO_10: U1.34 U4.4 | length 1125.1
  Top Layer w6: U4.4@2100,473.2 v1(2100,530) ; U1.34@2208.35,955.75 2230.45,955.75 2262,987.3 2262,1033.04 2271.46,1042.5 2365.5,1042.5 2470,938 2470,681 2434,645 v1(2415,645)
  Bottom Layer w6: v1(2100,530) 2319,530 2415,626 v1(2415,645)
GPIO_11: U1.35 U4.3 | length 1136.1
  Top Layer w6: U4.3@2119.68,473.2 2119.68,499.68 2130,510 v1(2215,510) ; U1.35@2208.35,971.5 2227.61,971.5 2249,992.88 2249,1042.13 2254,1047.13 2254,1048 2262,1056 2389,1056 2485,960 2485,665 v1(2460,640)
  Bottom Layer w6: v1(2215,510) 2330,510 v1(2460,640)
GPIO_12: R7.1 U1.36 U3.3 | length 969.8
  Top Layer w6: v1(1595,1125) 1595,1190 1601.89,1196.89 U3.3@1601.89,1249.17 ; R7.1@2215.32,1090 2208.35,1083.03 2208.35,1016 ; U1.36@2222.24,987.24 U1.36@2208.35,987.24 2208.35,1016 ; v1(2229,1016) 2208.35,1016
  Bottom Layer w6: v1(1595,1125) 1595,1085 1653,1027 1955,1027 1961,1021 2167.97,1021 2172.97,1016 v1(2229,1016)
GPIO_13: R8.1 U1.37 U3.1 | length 1070.1
  Top Layer w6: v1(1505,1290) 1551.22,1290 U3.1@1553.66,1287.56 ; U1.37@2180.79,1014.8 2180.79,1044.21 2187,1050.43 2187,1103.19 R8.1@2215.32,1131.51 2215.32,1210.32 2240,1235 v1(2240,1260)
  Bottom Layer w6: v1(1505,1290) 1520,1275 1963.13,1275 1967.13,1279 1982.87,1279 2001.87,1260 v1(2240,1260)
GPIO_16: R25.2 U1.38 U2.9 | length 1187.1
  Top Layer w6: R25.2@1339.69,1110 1540,1110 1565,1085 1790.37,1085 1868.14,1162.77 v1(1868.14,1191.78) ; U1.38@2165.04,1014.8 2165.04,1059.04 2175,1069 v1(2175,1150) 2171.31,1153.69 U2.9@2171.31,1242.56
  Bottom Layer w6: v1@1868.14,1188.02 v1(1868.14,1191.78) 1924.34,1135.58 1988.29,1135.58 2004.87,1119 2125.31,1119 2156.31,1150 v1(2175,1150)
GPIO_17: R26.1 U1.39 U2.8 U6.39 | length 1321.5
  Top Layer w6: U6.39@1218.5,1143.69 1438.38,1143.69 R26.1@1442,1147.32 1460.74,1147.32 1483.06,1125 1545,1125 1571.74,1098.26 1782.86,1098.26 1838.23,1153.64 v1(1838.23,1217.38) ; U1.39@2149.29,1014.8 2150,1015.51 v1(2150,1170) 2150,1239.52 2149.29,1240.23 U2.8@2151.62,1242.56
  Bottom Layer w6: v1(1838.23,1217.38) 1838.23,1213.83 1841.07,1216.67 1937.33,1216.67 2018,1136 2105.29,1136 2139.29,1170 v1(2150,1170)
GPIO_18: U1.40 U2.7 | length 230.5
  Top Layer w6: U2.7@2131.94,1242.56 2133.54,1240.95 2133.54,1180.41 2131,1177.87 2131,1162.13 2133.54,1159.59 U1.40@2133.54,1014.8
GPIO_19: R18.2 U1.41 U2.6 | length 585.2
  Top Layer w6: U2.6@2112.25,1242.56 v1(2112.25,1200) 2112.25,1184.75 2117.8,1179.2 U1.41@2117.8,1014.8
  Top Layer w10: v1(2390,1204) 2391,1205 R18.2@2465.31,1205
  Bottom Layer w6: v1(2112.25,1200) 2116.25,1204 v1(2390,1204)
GPIO_20: U1.42 U2.5 | length 231.7
  Top Layer w6: U2.5@2092.57,1242.56 2093.25,1241.87 2093.25,1186.78 2102.05,1177.98 U1.42@2102.05,1014.8
GPIO_21: R17.2 U1.43 U2.4 | length 765.1
  Top Layer w6: U2.4@2072.88,1242.56 2075,1240.44 2074.25,1239.7 v1(2074.25,1189.62) 2074.25,1168.75 2086.3,1156.7 U1.43@2086.3,1014.8
  Top Layer w10: v1(2398,1260) 2399.09,1258.91 R17.2@2575,1258.91
  Bottom Layer w6: v1(2074.25,1189.62) 2075,1189.62 2106.38,1221 2357,1221 2397,1261 v1(2398,1260)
